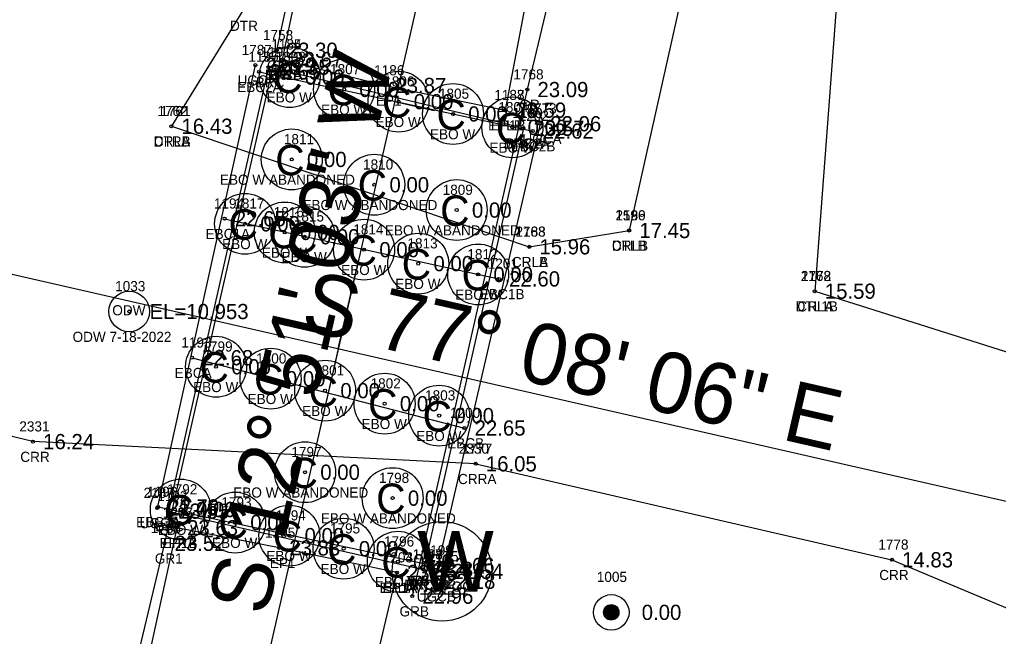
# Model space of a CAD drawing. Extents: x 2654414 to 2656963, y 761776 to 764965.
# Drawn here: x 2655685.5 to 2655781.9, y 763221.6 to 763282.4 of the extents above; entities that cross this region are included whole.
import ezdxf

# ---------------------------------------------------------------- set-up
doc = ezdxf.new("R2010")
doc.units = 0
for name, color, linetype in [('Default', 7, 'Continuous'), ('RD_EX_Bridge', 7, 'Continuous'), ('RD_EX_Bridge_txCode', 7, 'Continuous'), ('RD_EX_DV_Prop_txCode', 7, 'Continuous'), ('RD_EX_DV_PropPin', 7, 'Continuous'), ('RD_EX_GuardRail', 7, 'Continuous'), ('RD_EX_GuardRail_txCode', 7, 'Continuous'), ('RD_EX_H2O', 7, 'Continuous'), ('RD_EX_H2O_txCode', 7, 'Continuous'), ('RD_EX_Road', 7, 'Continuous'), ('RD_EX_Road_txCode', 7, 'Continuous'), ('RD_EX_TX_Bridge_ELEV', 7, 'Continuous'), ('RD_EX_TX_DV_Prop_ELEV', 7, 'Continuous'), ('RD_EX_TX_GuardRail_ELEV', 7, 'Continuous'), ('RD_EX_TX_H2O_ELEV', 7, 'Continuous'), ('RD_EX_TX_Road_ELEV', 7, 'Continuous'), ('RD_EX_TX_UT_ELEV', 7, 'Continuous'), ('RD_EX_UT', 7, 'Continuous'), ('RD_EX_UT_txCode', 7, 'Continuous'), ('RD_HC_Cl', 7, 'Continuous'), ('RD_HC_Data', 7, 'Continuous'), ('RD_HC_Data_Tic', 7, 'Continuous'), ('RD_SMD_Locator', 7, 'Continuous')]:
    doc.layers.add(name, color=color, linetype=linetype)

msp = doc.modelspace()

# ---------------------------------------------------------------- linework, layer by layer
at = {"layer": 'Default'}
for p, q in [((2656050.51, 764712.367), (2655383.263, 761787.511)), ((2655668.262, 763261.045), (2655813.766, 763227.813))]:
    msp.add_line(p, q, dxfattribs=at)
at = {"layer": 'RD_EX_Bridge'}
for p, q in [((2655709.094, 763277.237), (2655736.044, 763271.403)), ((2655735.127, 763271.676), (2655725.278, 763228.164)), ((2655705.695, 763262.758), (2655732.718, 763256.822)), ((2655702.489, 763249.051), (2655729.319, 763242.118)), ((2655699.134, 763234.341), (2655726.266, 763228.563))]:
    msp.add_line(p, q, dxfattribs=at)
msp.add_lwpolyline([(2655735.127, 763271.676), (2655710.015, 763277.697), (2655700.118, 763233.926), (2655725.278, 763228.164)], dxfattribs=at)
for centre in [(2655712.097, 763276.722), (2655717.462, 763275.51), (2655722.827, 763274.298), (2655728.192, 763273.087), (2655734.044, 763271.765), (2655712.307, 763268.605), (2655720.432, 763266.108), (2655728.557, 763263.611), (2655707.708, 763262.256), (2655711.617, 763261.406), (2655713.571, 763260.98), (2655719.434, 763259.705), (2655724.767, 763258.33), (2655730.671, 763257.26), (2655704.849, 763248.16), (2655710.222, 763246.982), (2655715.594, 763245.804), (2655721.455, 763244.518), (2655726.827, 763243.34), (2655713.617, 763237.76), (2655722.247, 763235.206), (2655701.373, 763234.08), (2655706.72, 763232.793), (2655712.067, 763231.507), (2655717.415, 763230.22), (2655722.762, 763228.933)]:
    msp.add_circle(centre, 3, dxfattribs=at)
at = {"layer": 'RD_EX_DV_PropPin'}
for p, q in [((2655743.05, 763223.746), (2655743.05, 763224.138)), ((2655743.085, 763223.644), (2655743.085, 763224.24)), ((2655743.12, 763223.573), (2655743.12, 763224.312)), ((2655743.155, 763223.516), (2655743.155, 763224.369)), ((2655743.19, 763223.468), (2655743.19, 763224.416)), ((2655743.225, 763223.427), (2655743.225, 763224.457)), ((2655743.26, 763223.391), (2655743.26, 763224.493)), ((2655743.295, 763223.36), (2655743.295, 763224.524)), ((2655743.33, 763223.332), (2655743.33, 763224.552)), ((2655743.365, 763223.308), (2655743.365, 763224.577)), ((2655743.4, 763223.286), (2655743.4, 763224.599)), ((2655743.435, 763223.267), (2655743.435, 763224.618)), ((2655743.47, 763223.249), (2655743.47, 763224.635)), ((2655743.505, 763223.235), (2655743.505, 763224.65)), ((2655743.54, 763223.222), (2655743.54, 763224.663)), ((2655743.575, 763223.211), (2655743.575, 763224.674)), ((2655743.61, 763223.202), (2655743.61, 763224.683)), ((2655743.645, 763223.194), (2655743.645, 763224.69)), ((2655743.68, 763223.188), (2655743.68, 763224.696)), ((2655743.715, 763223.184), (2655743.715, 763224.7)), ((2655743.75, 763223.182), (2655743.75, 763224.702)), ((2655743.785, 763223.181), (2655743.785, 763224.703)), ((2655743.82, 763223.182), (2655743.82, 763224.702)), ((2655743.855, 763223.184), (2655743.855, 763224.7)), ((2655743.89, 763223.188), (2655743.89, 763224.696)), ((2655743.925, 763223.194), (2655743.925, 763224.69)), ((2655743.96, 763223.202), (2655743.96, 763224.683)), ((2655743.995, 763223.211), (2655743.995, 763224.674)), ((2655744.03, 763223.222), (2655744.03, 763224.663)), ((2655744.065, 763223.235), (2655744.065, 763224.65)), ((2655744.1, 763223.249), (2655744.1, 763224.635)), ((2655744.135, 763223.267), (2655744.135, 763224.618)), ((2655744.17, 763223.286), (2655744.17, 763224.599)), ((2655744.205, 763223.308), (2655744.205, 763224.577)), ((2655744.24, 763223.332), (2655744.24, 763224.552)), ((2655744.275, 763223.36), (2655744.275, 763224.524)), ((2655744.31, 763223.391), (2655744.31, 763224.493)), ((2655744.345, 763223.427), (2655744.345, 763224.457)), ((2655744.38, 763223.468), (2655744.38, 763224.416)), ((2655744.415, 763223.516), (2655744.415, 763224.369)), ((2655744.45, 763223.573), (2655744.45, 763224.312)), ((2655744.485, 763223.644), (2655744.485, 763224.24)), ((2655744.52, 763223.746), (2655744.52, 763224.138))]:
    msp.add_line(p, q, dxfattribs=at)
for radius in [1.75, 0.761]:
    msp.add_circle((2655743.785, 763223.942), radius, dxfattribs=at)
at = {"layer": 'RD_EX_GuardRail'}
for points in [[(2655721.322, 763327.656), (2655710.813, 763279.368), (2655699.76, 763230.752), (2655688.364, 763182.859)], [(2655746.729, 763322.574), (2655735.512, 763275.495), (2655724.177, 763225.541)]]:
    msp.add_lwpolyline(points, dxfattribs=at)
at = {"layer": 'RD_EX_H2O'}
for p, q in [((2655700.442, 763271.878), (2655735.703, 763259.987)), ((2655735.703, 763259.987), (2655745.55, 763261.596))]:
    msp.add_line(p, q, dxfattribs=at)
for points in [[(2655866.204, 763781.921), (2655858.432, 763782.117), (2655853.293, 763757.631), (2655831.207, 763662.135), (2655807.206, 763570.585), (2655787.764, 763479.914), (2655766.407, 763384.859), (2655751.377, 763287.622), (2655745.55, 763261.596)], [(2655866.204, 763781.921), (2655866.814, 763773.877), (2655862.675, 763756.122), (2655841.509, 763659.39), (2655821.676, 763567.674), (2655800.982, 763476.962), (2655780.087, 763381.342), (2655766.41, 763289.678), (2655763.828, 763255.61)], [(2655761.665, 763536.786), (2655754.619, 763487.895), (2655730.783, 763392.483), (2655710.333, 763297.534), (2655707.493, 763283.282), (2655700.442, 763271.878)], [(2655763.828, 763255.61), (2655817.49, 763238.629), (2655914.797, 763213.379), (2655950.664, 763206.207), (2656007.419, 763189.451), (2656109.246, 763159.235), (2656208.325, 763130.475)], [(2655730.427, 763238.591), (2655686.811, 763240.778), (2655666.677, 763245.606), (2655638.832, 763240.96), (2655580.221, 763226.713), (2655520.12, 763186.009), (2655467.249, 763134.056), (2655436.951, 763097.369), (2655374.527, 763041.274), (2655306.291, 762970.795)], [(2655730.427, 763238.591), (2655771.44, 763229.126), (2655791.171, 763220.85), (2655791.171, 763220.85), (2655810.242, 763214.703), (2655909.39, 763186.926), (2656001.093, 763162.175), (2656103.256, 763131.883), (2656200.939, 763101.915)]]:
    msp.add_lwpolyline(points, dxfattribs=at)
for radius in [2, 0.15]:
    msp.add_circle((2655696.291, 763253.608), radius, dxfattribs=at)
at = {"layer": 'RD_EX_Road'}
for points in [[(2656041.724, 764723.313), (2656018.496, 764622.032), (2656002.752, 764552.488), (2655997.431, 764530.019), (2655974.744, 764429.641), (2655952.966, 764333.569), (2655930.525, 764235.7), (2655909.181, 764142.933), (2655887.927, 764050.569), (2655866.907, 763957.263), (2655846.823, 763869.533), (2655845.209, 763862.22), (2655839.99, 763839.712), (2655823.384, 763766.659), (2655801.328, 763669.929), (2655780.028, 763576.53), (2655774.262, 763551.849), (2655771.37, 763539.86), (2655759.09, 763486.901), (2655736.944, 763391.717), (2655715.19, 763296.767), (2655711.354, 763278.447)], [(2655852.894, 763796.343), (2655850.73, 763786.523), (2655844.88, 763760.966), (2655822.623, 763664.698), (2655801.116, 763571.821), (2655780.323, 763481.637), (2655758.157, 763386.375), (2655736.727, 763291.266), (2655733.325, 763273.462)], [(2655711.354, 763278.447), (2655721.512, 763275.897), (2655733.325, 763273.462)], [(2655700.994, 763232.279), (2655693.552, 763198.573), (2655671.649, 763102.037), (2655649.038, 763001.061), (2655627.271, 762906.233), (2655604.996, 762809.365), (2655598.992, 762783.09), (2655583.655, 762714.137), (2655561.97, 762618.323), (2655556.356, 762593.843), (2655548.114, 762557.141), (2655540.102, 762522.478), (2655518.03, 762425.04), (2655496.479, 762329.558), (2655475.552, 762236.625), (2655473.199, 762226.142), (2655466.574, 762197.504), (2655460.058, 762168.164), (2655454.261, 762143.776), (2655432.5, 762049.878), (2655410.7, 761955.515), (2655388.166, 761858.426), (2655373.501, 761793.951)], [(2655722.661, 763227.867), (2655711.06, 763230.301), (2655700.994, 763232.279)], [(2655722.661, 763227.867), (2655714.474, 763193.228), (2655692.888, 763097.257), (2655670.037, 762995.178), (2655648.569, 762900.673)]]:
    msp.add_lwpolyline(points, dxfattribs=at)
at = {"layer": 'RD_EX_UT'}
for p, q in [((2655708.716, 763277.9), (2655699.055, 763234.23)), ((2655736.774, 763272.123), (2655726.352, 763227.009)), ((2655724.986, 763225.772), (2655729.615, 763225.772))]:
    msp.add_line(p, q, dxfattribs=at)
msp.add_circle((2655727.114, 763227.98), 4.908, dxfattribs=at)
at = {"layer": 'RD_HC_Cl'}
for p, q in [((2656050.51, 764712.367), (2655383.263, 761787.511)), ((2655668.262, 763261.045), (2655813.766, 763227.813))]:
    msp.add_line(p, q, dxfattribs=at)
at = {"layer": 'RD_HC_Data_Tic'}
for p, q in [((2655722.447, 763274.313), (2655726.347, 763273.424)), ((2655716.894, 763249.938), (2655718.675, 763257.737)), ((2655716.894, 763249.938), (2655715.113, 763242.139))]:
    msp.add_line(p, q, dxfattribs=at)
at = {"layer": 'RD_SMD_Locator'}
for centre in [(2655710.813, 763279.368), (2655708.716, 763277.9), (2655711.354, 763278.447), (2655711.354, 763278.447), (2655709.094, 763277.237), (2655710.015, 763277.697), (2655712.097, 763276.722), (2655721.512, 763275.897), (2655717.462, 763275.51), (2655735.512, 763275.495), (2655722.827, 763274.298), (2655728.192, 763273.087), (2655733.325, 763273.462), (2655733.325, 763273.462), (2655736.774, 763272.123), (2655700.442, 763271.878), (2655700.442, 763271.878), (2655734.044, 763271.765), (2655735.127, 763271.676), (2655735.127, 763271.676), (2655736.044, 763271.403), (2655712.307, 763268.605), (2655720.432, 763266.108), (2655728.557, 763263.611), (2655705.695, 763262.758), (2655707.708, 763262.256), (2655711.617, 763261.406), (2655745.55, 763261.596), (2655745.55, 763261.596), (2655713.571, 763260.98), (2655719.434, 763259.705), (2655735.703, 763259.987), (2655735.703, 763259.987), (2655724.767, 763258.33), (2655730.671, 763257.26), (2655732.718, 763256.822), (2655763.828, 763255.61), (2655763.828, 763255.61), (2655702.489, 763249.051), (2655704.85, 763248.16), (2655710.222, 763246.982), (2655715.594, 763245.804), (2655721.455, 763244.518), (2655726.827, 763243.34), (2655729.319, 763242.118), (2655686.811, 763240.778), (2655730.427, 763238.591), (2655730.427, 763238.591), (2655713.617, 763237.76), (2655699.134, 763234.341), (2655722.247, 763235.206), (2655699.055, 763234.23), (2655700.118, 763233.926), (2655701.373, 763234.08), (2655706.72, 763232.793), (2655700.994, 763232.279), (2655700.994, 763232.279), (2655712.067, 763231.507), (2655699.76, 763230.752), (2655711.06, 763230.301), (2655717.415, 763230.22), (2655722.762, 763228.933), (2655726.266, 763228.563), (2655771.44, 763229.126), (2655722.661, 763227.867), (2655722.661, 763227.867), (2655725.278, 763228.164), (2655725.278, 763228.164), (2655727.114, 763227.98), (2655726.352, 763227.009), (2655724.177, 763225.541), (2655743.785, 763223.942)]:
    msp.add_circle(centre, 0.15, dxfattribs=at)

# ---------------------------------------------------------------- texts
at = {"layer": 'RD_EX_Bridge'}
for p in [(2655710.467, 763275.161), (2655715.831, 763273.949), (2655721.196, 763272.737), (2655726.561, 763271.525), (2655732.414, 763270.203), (2655710.676, 763267.044), (2655718.801, 763264.547), (2655726.926, 763262.05), (2655706.077, 763260.694), (2655709.986, 763259.844), (2655711.94, 763259.419), (2655717.803, 763258.143), (2655723.137, 763256.769), (2655729.04, 763255.699), (2655703.219, 763246.599), (2655708.591, 763245.42), (2655713.963, 763244.242), (2655719.824, 763242.957), (2655725.196, 763241.778), (2655711.987, 763236.198), (2655720.617, 763233.645), (2655699.742, 763232.519), (2655705.089, 763231.232), (2655710.437, 763229.945), (2655715.784, 763228.658), (2655721.131, 763227.372)]:
    msp.add_text('C', height=3, dxfattribs=at).set_placement(p)
at = {"layer": 'RD_EX_Bridge_txCode'}
for s, p in [('1195', (2655708.031, 763278.237)), ('1191', (2655709.236, 763278.697)), ('1808', (2655710.711, 763278.222)), ('1807', (2655716.076, 763277.01)), ('EBC2A', (2655706.928, 763275.237)), ('BRC', (2655708.763, 763275.697)), ('1806', (2655721.418, 763275.798)), ('EBO W', (2655709.83, 763274.222)), ('1805', (2655726.806, 763274.587)), ('1804', (2655732.659, 763273.265)), ('EBO W', (2655715.194, 763273.01)), ('1190', (2655734.025, 763272.676)), ('1189', (2655734.064, 763272.676)), ('1202', (2655734.658, 763272.403)), ('EBO W', (2655720.559, 763271.798)), ('EBO W', (2655725.924, 763270.587)), ('1811', (2655711.528, 763270.105)), ('EBO W', (2655731.777, 763269.265)), ('BRC1A', (2655733.221, 763269.676)), ('BRCA', (2655733.387, 763269.676)), ('EBC2B', (2655733.894, 763269.403)), ('1810', (2655719.33, 763267.608)), ('EBO W ABANDONED', (2655705.228, 763266.105)), ('1809', (2655727.171, 763265.111)), ('1194', (2655704.632, 763263.758)), ('1817', (2655706.645, 763263.756)), ('EBO W ABANDONED', (2655713.353, 763263.608)), ('1816', (2655710.53, 763262.906)), ('1815', (2655712.508, 763262.48)), ('EBC1A', (2655703.813, 763260.758)), ('1814', (2655718.371, 763261.205)), ('EBO W ABANDONED', (2655721.478, 763261.111)), ('EBO W', (2655705.44, 763259.756)), ('1813', (2655723.704, 763259.83)), ('EBO W', (2655709.349, 763258.906)), ('1812', (2655729.608, 763258.76)), ('EBO W', (2655711.303, 763258.48)), ('1201', (2655731.615, 763257.822)), ('EBO W', (2655717.166, 763257.205)), ('EBO W', (2655722.5, 763255.83)), ('EBO W', (2655728.403, 763254.76)), ('EBC1B', (2655730.852, 763254.822)), ('1193', (2655701.426, 763250.051)), ('1799', (2655703.503, 763249.66)), ('1800', (2655708.797, 763248.482)), ('EBCA', (2655700.772, 763247.051)), ('1801', (2655714.492, 763247.304)), ('1802', (2655720.069, 763246.018)), ('EBO W', (2655702.582, 763245.66)), ('EBO W', (2655707.954, 763244.482)), ('1803', (2655725.441, 763244.84)), ('EBO W', (2655713.326, 763243.304)), ('1200', (2655727.894, 763243.118)), ('EBO W', (2655719.187, 763242.018)), ('EBO W', (2655724.559, 763240.84)), ('1797', (2655712.271, 763239.26)), ('EBCB', (2655727.618, 763240.118)), ('1798', (2655720.901, 763236.706)), ('1792', (2655700.026, 763235.58)), ('1196', (2655698.047, 763235.341)), ('1192', (2655699.055, 763234.926)), ('EBO W ABANDONED', (2655706.539, 763235.26)), ('1793', (2655705.373, 763234.293)), ('1794', (2655710.721, 763233.007)), ('EBO W ABANDONED', (2655715.169, 763232.706)), ('EBC3A', (2655696.969, 763232.341)), ('BRC', (2655698.866, 763231.926)), ('EBO W', (2655699.105, 763231.58)), ('1795', (2655716.068, 763231.72)), ('EBO W', (2655704.452, 763230.293)), ('1796', (2655721.392, 763230.433)), ('EBO W', (2655709.8, 763229.007)), ('1197', (2655724.215, 763229.164)), ('1198', (2655724.215, 763229.164)), ('1199', (2655725.203, 763229.563)), ('EBO W', (2655715.147, 763227.72)), ('EBO W', (2655720.494, 763226.433)), ('BRC1B', (2655723.389, 763226.164)), ('BRCB', (2655723.554, 763226.164)), ('EBC3B', (2655724.117, 763226.563))]:
    msp.add_text(s, height=1, dxfattribs=at).set_placement(p)
at = {"layer": 'RD_EX_DV_Prop_txCode'}
msp.add_text('1005', height=1, dxfattribs=at).set_placement((2655742.36, 763226.942))
at = {"layer": 'RD_EX_GuardRail_txCode'}
for s, p in [('1758', (2655709.466, 763280.368)), ('GR1', (2655709.868, 763277.368)), ('1768', (2655734.142, 763276.495)), ('GR', (2655734.733, 763273.495)), ('1788', (2655698.413, 763231.752)), ('GR1', (2655698.815, 763228.752)), ('1776', (2655722.807, 763226.541)), ('GRB', (2655722.925, 763223.541))]:
    msp.add_text(s, height=1, dxfattribs=at).set_placement(p)
at = {"layer": 'RD_EX_H2O'}
msp.add_text('ODW', height=1, dxfattribs=at).set_placement((2655694.625, 763253.232))
at = {"layer": 'RD_EX_H2O_txCode'}
for s, p in [('DTR', (2655706.225, 763281.282)), ('1762', (2655699.072, 763272.878)), ('1761', (2655699.355, 763272.878)), ('CRLA', (2655698.725, 763269.878)), ('DTRB', (2655698.702, 763269.878)), ('2189', (2655744.203, 763262.596)), ('1596', (2655744.179, 763262.596)), ('2188', (2655734.356, 763260.987)), ('1763', (2655734.333, 763260.987)), ('CRLB', (2655743.849, 763259.596)), ('DTLB', (2655743.833, 763259.596)), ('CRLA', (2655733.986, 763257.987)), ('CRLB', (2655734.002, 763257.987)), ('2168', (2655762.458, 763256.61)), ('1772', (2655762.482, 763256.61)), ('1033', (2655694.906, 763255.608)), ('DTL1B', (2655761.947, 763253.61)), ('CRLA', (2655762.112, 763253.61)), ('ODW 7-18-2022', (2655690.709, 763250.608)), ('2331', (2655685.465, 763241.778)), ('2330', (2655728.758, 763239.591)), ('1777', (2655729.081, 763239.591)), ('CRR', (2655685.559, 763238.778)), ('CRRA', (2655728.687, 763236.591)), ('CRRA', (2655728.687, 763236.591)), ('1778', (2655770.094, 763230.126)), ('CRR', (2655770.188, 763227.126))]:
    msp.add_text(s, height=1, dxfattribs=at).set_placement(p)
at = {"layer": 'RD_EX_Road_txCode'}
for s, p in [('1184', (2655710.291, 763279.447)), ('1185', (2655710.291, 763279.447)), ('1186', (2655720.425, 763276.897)), ('EPRB', (2655709.653, 763276.447)), ('EP1A', (2655709.944, 763276.447)), ('1187', (2655732.262, 763274.462)), ('1188', (2655732.262, 763274.462)), ('EP1', (2655720.59, 763273.897)), ('EPLB', (2655731.648, 763271.462)), ('EP1B', (2655731.932, 763271.462)), ('1206', (2655699.585, 763233.279)), ('1207', (2655699.608, 763233.279)), ('1205', (2655709.674, 763231.301)), ('EPRA', (2655699.278, 763230.279)), ('EP1B', (2655699.601, 763230.279)), ('1203', (2655721.275, 763228.867)), ('1204', (2655721.275, 763228.867)), ('EP1', (2655710.138, 763228.301)), ('EPLA', (2655720.968, 763225.867)), ('EP1A', (2655721.252, 763225.867))]:
    msp.add_text(s, height=1, dxfattribs=at).set_placement(p)
at = {"layer": 'RD_EX_TX_Bridge_ELEV'}
for s, p in [('22.65', (2655710.094, 763276.487)), ('23.35', (2655711.015, 763276.947)), ('0.00', (2655713.597, 763275.972)), ('0.00', (2655718.962, 763274.76)), ('0.00', (2655724.327, 763273.548)), ('0.00', (2655729.692, 763272.337)), ('0.00', (2655735.544, 763271.015)), ('23.57', (2655736.127, 763270.926)), ('23.57', (2655736.127, 763270.926)), ('22.62', (2655737.044, 763270.653)), ('0.00', (2655713.807, 763267.855)), ('0.00', (2655721.932, 763265.358)), ('0.00', (2655730.057, 763262.861)), ('22.65', (2655706.695, 763262.008)), ('0.00', (2655709.208, 763261.506)), ('0.00', (2655713.117, 763260.656)), ('0.00', (2655715.071, 763260.23)), ('0.00', (2655720.934, 763258.955)), ('0.00', (2655726.267, 763257.58)), ('0.00', (2655732.171, 763256.51)), ('22.60', (2655733.718, 763256.072)), ('22.68', (2655703.489, 763248.301)), ('0.00', (2655706.35, 763247.41)), ('0.00', (2655711.722, 763246.232)), ('0.00', (2655717.094, 763245.054)), ('0.00', (2655722.955, 763243.768)), ('0.00', (2655728.327, 763242.59)), ('22.65', (2655730.319, 763241.368)), ('0.00', (2655715.117, 763237.01)), ('0.00', (2655723.747, 763234.456)), ('22.70', (2655700.134, 763233.591)), ('23.55', (2655701.118, 763233.176)), ('0.00', (2655702.873, 763233.33)), ('0.00', (2655708.22, 763232.043)), ('0.00', (2655713.567, 763230.757)), ('0.00', (2655718.915, 763229.47)), ('0.00', (2655724.262, 763228.183)), ('23.34', (2655726.278, 763227.414)), ('23.34', (2655726.278, 763227.414)), ('22.66', (2655727.266, 763227.813))]:
    msp.add_text(s, height=1.5, dxfattribs=at).set_placement(p)
at = {"layer": 'RD_EX_TX_DV_Prop_ELEV'}
msp.add_text('0.00', height=1.5, dxfattribs=at).set_placement((2655746.785, 763223.192))
at = {"layer": 'RD_EX_TX_GuardRail_ELEV'}
for s, p in [('23.30', (2655711.813, 763278.618)), ('23.09', (2655736.512, 763274.745)), ('23.52', (2655700.76, 763230.002)), ('22.96', (2655725.177, 763224.791))]:
    msp.add_text(s, height=1.5, dxfattribs=at).set_placement(p)
at = {"layer": 'RD_EX_TX_H2O_ELEV'}
for s, p in [('16.43', (2655701.442, 763271.128)), ('16.43', (2655701.442, 763271.128)), ('17.45', (2655746.55, 763260.846)), ('17.45', (2655746.55, 763260.846)), ('15.96', (2655736.703, 763259.237)), ('15.96', (2655736.703, 763259.237)), ('15.59', (2655764.828, 763254.86)), ('15.59', (2655764.828, 763254.86)), ('EL=10.953', (2655698.291, 763252.858)), ('16.24', (2655687.811, 763240.028)), ('16.05', (2655731.427, 763237.841)), ('16.05', (2655731.427, 763237.841)), ('14.83', (2655772.44, 763228.376))]:
    msp.add_text(s, height=1.5, dxfattribs=at).set_placement(p)
at = {"layer": 'RD_EX_TX_Road_ELEV'}
for s, p in [('23.67', (2655712.354, 763277.697)), ('23.67', (2655712.354, 763277.697)), ('23.87', (2655722.512, 763275.147)), ('23.59', (2655734.325, 763272.712)), ('23.59', (2655734.325, 763272.712)), ('23.63', (2655701.994, 763231.529)), ('23.63', (2655701.994, 763231.529)), ('23.83', (2655712.06, 763229.551)), ('23.55', (2655723.661, 763227.117)), ('23.55', (2655723.661, 763227.117))]:
    msp.add_text(s, height=1.5, dxfattribs=at).set_placement(p)
at = {"layer": 'RD_EX_TX_UT_ELEV'}
for s, p in [('21.29', (2655709.716, 763277.15)), ('22.06', (2655737.774, 763271.373)), ('21.45', (2655700.055, 763233.48)), ('21.54', (2655728.114, 763227.23)), ('22.18', (2655727.352, 763226.259))]:
    msp.add_text(s, height=1.5, dxfattribs=at).set_placement(p)
at = {"layer": 'RD_EX_UT'}
msp.add_text('W', height=6, dxfattribs=at).set_placement((2655724.649, 763225.979))
at = {"layer": 'RD_EX_UT_txCode'}
for s, p in [('1787', (2655707.369, 763278.9)), ('UGCA', (2655706.968, 763275.9)), ('1773', (2655735.427, 763273.123)), ('UGCA', (2655735.026, 763270.123)), ('2187', (2655697.709, 763235.23)), ('UGCB', (2655697.323, 763232.23)), ('1775', (2655725.767, 763228.98)), ('1774', (2655725.005, 763228.009)), ('WTS FOC', (2655723.901, 763225.98)), ('UGCB', (2655724.62, 763225.009))]:
    msp.add_text(s, height=1, dxfattribs=at).set_placement(p)
at = {"layer": 'RD_HC_Data'}
for s, rotation, p in [('S 12%%d 51\' 03" W', 77.14905, (2655709.823, 763223.47)), ('S 77%%d 08\' 06" E', 347.13492, (2655713.026, 763251.847))]:
    msp.add_text(s, height=6, rotation=rotation, dxfattribs=at).set_placement(p)

doc.saveas('drawing.dxf')
